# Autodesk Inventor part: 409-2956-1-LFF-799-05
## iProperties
Created: 2010-11
Part Number: 409-2956-1-LFF-799-05
Material: 3/4" OD TUBE - SS
Document SubType Name: Modeling
Designer: S. Boerckel
Engineer: Steve Boerckel
Mass: 731.966 g
Surface Area: 1099.2 cm^2
Volume: 90.5898 cm^3
Density: 8.08 g/cm^3
Description: DRAIN TUBING
Length: 39.521 in
Author: S. Boerckel
Revision Number: 0
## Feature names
1. TaggingFeature1
